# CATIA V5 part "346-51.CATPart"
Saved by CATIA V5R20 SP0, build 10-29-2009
Part number: 346-51
Definition: NONE
Nomenclature: 346-51
Source: Unknown
Description: 346-51
Bounding box of the stored display mesh (mm): x 0 to 100, y -51.5 to 51.5, z -51.5 to 51.5
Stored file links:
  C:\Users\Utente\Desktop\IO LAVORO\3D X SITO CF\X SITO\3D files 346\346-51.CATPart
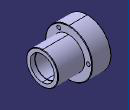
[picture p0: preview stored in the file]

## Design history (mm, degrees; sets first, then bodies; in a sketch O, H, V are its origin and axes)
Body1 "346-51" (main body)
  Solid1: solid without history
